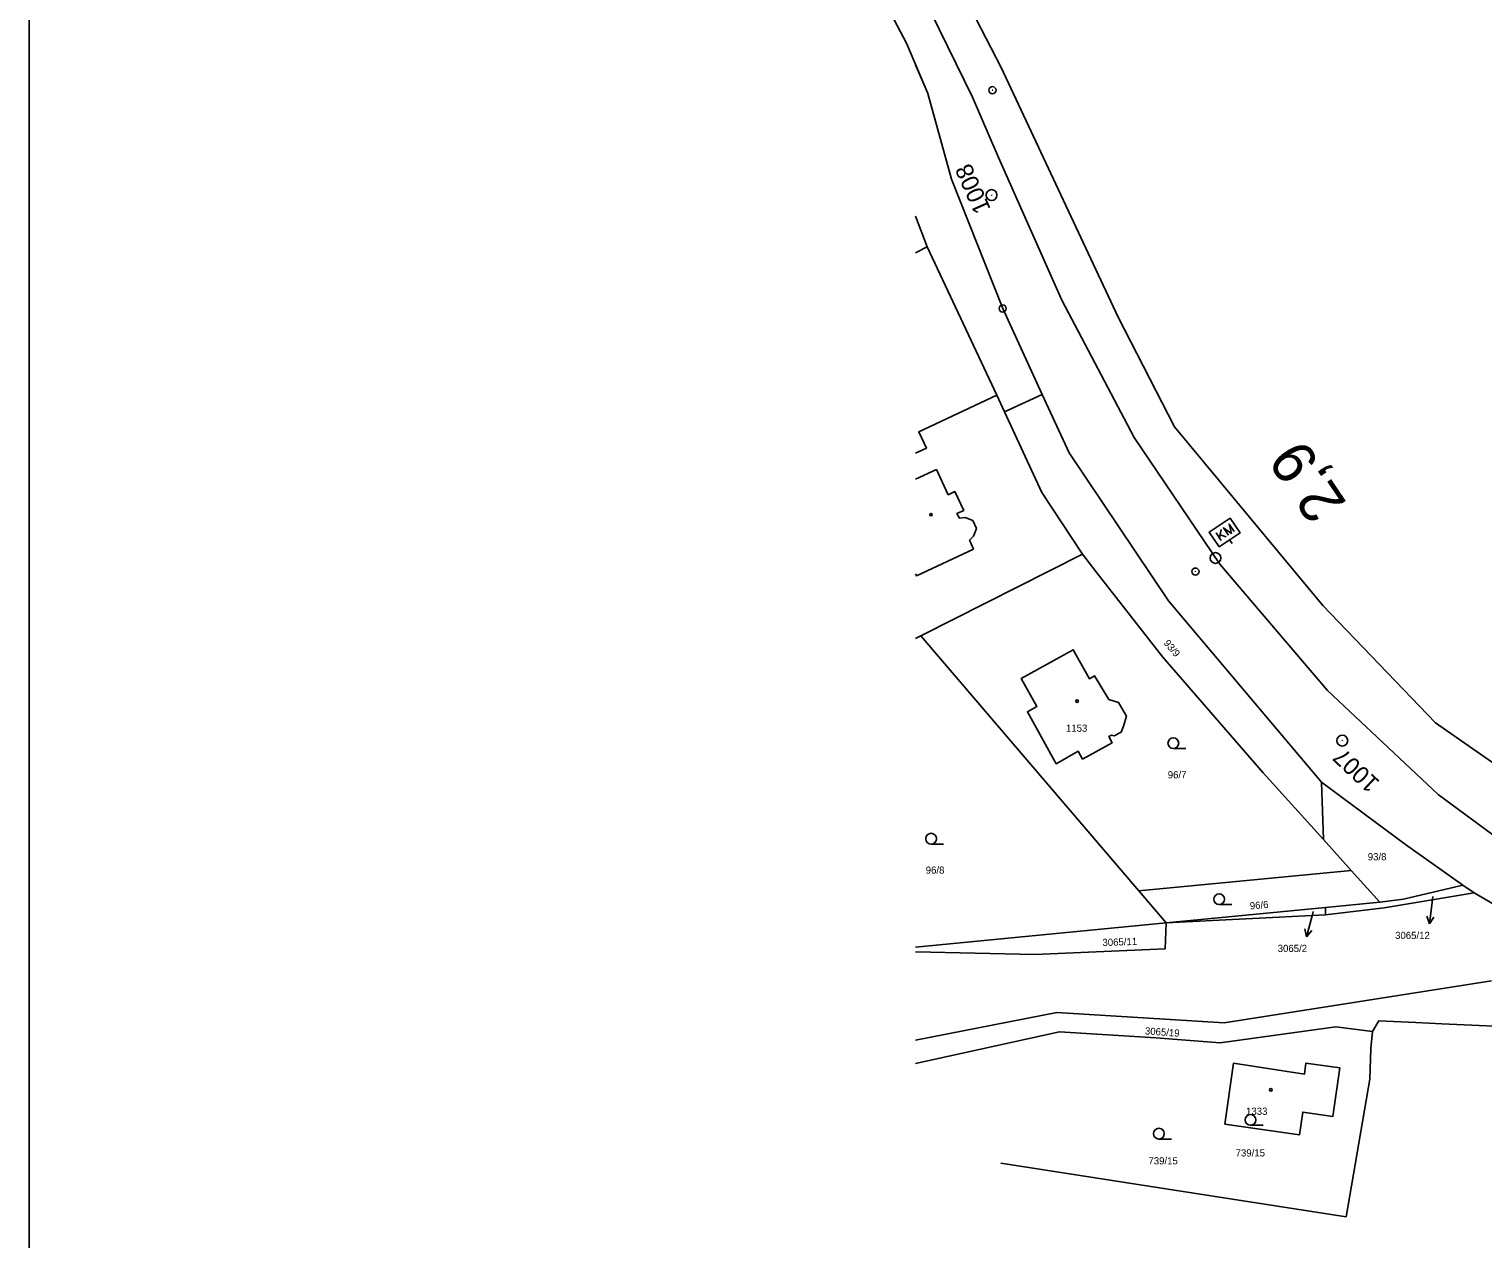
# Model space of a CAD drawing. Extents: x -728800 to -728100, y -1073200 to -1072700.
# Drawn here: x -728800 to -728597.5, y -1073060.8 to -1072892.3 of the extents above; entities that cross this region are included whole.
import ezdxf

# ---------------------------------------------------------------- set-up
doc = ezdxf.new("R2010")
doc.units = 0
for name, color, linetype in [('A1_OBVOD Spravy železnic', 7, 'Continuous'), ('B6_JŽM', 7, 'Continuous'), ('B7_Bodové pole', 7, 'Continuous'), ('K_01_Hranice parcel', 7, 'Continuous'), ('K_02_Parcelní čísla', 7, 'Continuous'), ('K_03_Značky druhu pozemku', 7, 'Continuous'), ('K_05_Značky stavební objekty', 7, 'Continuous'), ('K_07_Pop  PČ popisy', 7, 'Continuous')]:
    doc.layers.add(name, color=color, linetype=linetype)

msp = doc.modelspace()

# ---------------------------------------------------------------- linework, layer by layer
at = {"layer": 'A1_OBVOD Spravy železnic'}
for points in [[(-728681.24, -1072865.51), (-728664.64, -1072897.67), (-728648.31, -1072932.44), (-728640.48, -1072947.72), (-728619.81, -1072972.56), (-728604.14, -1072988.92), (-728582.13, -1073004.22)], [(-728594.83, -1073014.86), (-728598.74, -1073012.6), (-728600.31, -1073011.5), (-728608.33, -1073005.87), (-728620.02, -1072997.18), (-728641.33, -1072971.93), (-728655.13, -1072951.34), (-728658.89, -1072943.19), (-728664.41, -1072931.23), (-728671.52, -1072913.23), (-728674.84, -1072901.32), (-728677.82, -1072894.3), (-728686.27, -1072878.28)]]:
    msp.add_lwpolyline(points, dxfattribs=at)
at = {"layer": 'B6_JŽM'}
for p, q in [((-728665.89, -1072900.84), (-728665.79, -1072900.84)), ((-728664.46, -1072931.23), (-728664.36, -1072931.23)), ((-728634.69, -1072962.47), (-728634, -1072963.51)), ((-728634, -1072962.01), (-728634.23, -1072963.16)), ((-728634.14, -1072962.74), (-728633.3, -1072963.04)), ((-728632.46, -1072963.97), (-728632.81, -1072963.45)), ((-728637.54, -1072967.9), (-728637.59, -1072967.82))]:
    msp.add_line(p, q, dxfattribs=at)
for points in [[(-728800, -1073200), (-728800, -1072700), (-728100, -1072700), (-728100, -1073200), (-728800, -1073200)], [(-728300.81, -1073024.35), (-728320.8, -1073026.91), (-728374.01, -1073033.72), (-728429.1, -1073040.75), (-728461.93, -1073044.27), (-728481.2, -1073044.81), (-728499.35, -1073043.65), (-728506.01, -1073042.74), (-728514.57, -1073041.33), (-728535.85, -1073036), (-728561.35, -1073026.11), (-728583.96, -1073013.52), (-728603.76, -1072998.89), (-728619.19, -1072984.42), (-728634.19, -1072966.82), (-728646.08, -1072949.19), (-728656.18, -1072930.07), (-728664.99, -1072910.23), (-728668.63, -1072901.81), (-728681.25, -1072876.02), (-728691.89, -1072859.66)], [(-728632.96, -1072962.81), (-728633.66, -1072961.77), (-728632.56, -1072962.54), (-728632.87, -1072961.24), (-728632.17, -1072962.28)]]:
    msp.add_lwpolyline(points, dxfattribs=at)
msp.add_lwpolyline([(-728634.25, -1072964.42), (-728635.64, -1072962.37), (-728632.75, -1072960.42), (-728631.36, -1072962.47)], close=True, dxfattribs=at)
for centre, radius in [((-728665.84, -1072900.84), 0.499), ((-728664.41, -1072931.23), 0.499), ((-728634.77, -1072965.97), 0.75), ((-728637.57, -1072967.86), 0.5)]:
    msp.add_circle(centre, radius, dxfattribs=at)
at = {"layer": 'B7_Bodové pole'}
for p, q in [((-728665.94, -1072915.49), (-728665.98, -1072915.4)), ((-728617.07, -1072991.42), (-728617.15, -1072991.35))]:
    msp.add_line(p, q, dxfattribs=at)
for centre in [(-728665.96, -1072915.44), (-728617.11, -1072991.39)]:
    msp.add_circle(centre, 0.756, dxfattribs=at)
at = {"layer": 'K_01_Hranice parcel'}
for p, q in [((-728676.53, -1072918.38), (-728674.91, -1072922.64)), ((-728674.91, -1072922.64), (-728665.22, -1072943.32)), ((-728664.14, -1072945.63), (-728658.89, -1072943.19)), ((-728665.22, -1072943.32), (-728664.14, -1072945.63)), ((-728653.3, -1072965.44), (-728675.82, -1072976.81)), ((-728651.42, -1072967.85), (-728653.3, -1072965.44)), ((-728675.82, -1072976.81), (-728645.47, -1073012.3)), ((-728620.02, -1072997.18), (-728619.75, -1073005.17)), ((-728615.86, -1073009.48), (-728619.75, -1073005.17)), ((-728615.86, -1073009.48), (-728645.47, -1073012.3)), ((-728611.9, -1073013.87), (-728615.86, -1073009.48)), ((-728600.31, -1073011.5), (-728598.74, -1073012.6)), ((-728645.47, -1073012.3), (-728641.66, -1073016.76)), ((-728619.47, -1073014.61), (-728611.9, -1073013.87)), ((-728598.74, -1073012.6), (-728594.83, -1073014.86)), ((-728641.66, -1073016.76), (-728619.47, -1073014.61)), ((-728641.66, -1073016.76), (-728619.45, -1073015.63)), ((-728619.45, -1073015.63), (-728619.47, -1073014.61)), ((-728613.14, -1073034.24), (-728612.89, -1073031.9)), ((-728664.69, -1073050.2), (-728647.33, -1073052.89)), ((-728647.33, -1073052.89), (-728616.56, -1073057.69))]:
    msp.add_line(p, q, dxfattribs=at)
for points in [[(-728658.89, -1072943.19), (-728664.41, -1072931.23), (-728671.52, -1072913.23), (-728674.84, -1072901.32), (-728676.53, -1072897.33)], [(-728676.53, -1072923.46), (-728674.91, -1072922.64)], [(-728658.89, -1072943.19), (-728655.13, -1072951.34), (-728641.33, -1072971.93), (-728620.02, -1072997.18)], [(-728665.22, -1072943.32), (-728676.11, -1072948.38), (-728675.03, -1072950.69), (-728676.53, -1072951.39)], [(-728664.14, -1072945.63), (-728658.98, -1072956.84), (-728653.3, -1072965.44)], [(-728676.53, -1072955.01), (-728673.63, -1072953.66), (-728671.99, -1072957.16), (-728671.07, -1072956.72), (-728669.83, -1072959.34), (-728670.78, -1072959.75), (-728670.44, -1072960.42), (-728669.64, -1072960.34), (-728668.55, -1072960.74), (-728668.06, -1072961.84), (-728668.47, -1072962.95), (-728669.01, -1072963.48), (-728668.94, -1072963.65), (-728668.49, -1072964.73), (-728676.42, -1072968.43), (-728676.53, -1072968.18)], [(-728619.75, -1073005.17), (-728628.12, -1072995.9), (-728642.12, -1072979.76), (-728651.42, -1072967.85)], [(-728675.82, -1072976.81), (-728676.45, -1072977.13), (-728676.53, -1072977.17)], [(-728649.64, -1072985.67), (-728648.26, -1072986.08), (-728647.18, -1072987.97), (-728647.58, -1072989.39), (-728647.91, -1072990.21), (-728648.9, -1072990.74), (-728649.27, -1072990.62), (-728649.61, -1072990.81), (-728649.16, -1072991.69), (-728653.29, -1072993.97), (-728653.91, -1072992.88), (-728656.95, -1072994.61), (-728660.97, -1072987.38), (-728659.66, -1072986.65), (-728661.82, -1072982.76), (-728654.58, -1072978.73), (-728652.33, -1072982.79), (-728651.61, -1072982.39), (-728649.64, -1072985.67)], [(-728620.02, -1072997.18), (-728608.33, -1073005.87), (-728600.31, -1073011.5)], [(-728611.9, -1073013.87), (-728608.61, -1073013.46), (-728600.31, -1073011.5)], [(-728619.45, -1073015.63), (-728611.28, -1073014.65), (-728598.74, -1073012.6)], [(-728641.66, -1073016.76), (-728641.79, -1073020.38), (-728659.93, -1073021.15), (-728676.53, -1073020.82)], [(-728676.53, -1073020.14), (-728641.66, -1073016.76)], [(-728676.53, -1073033.08), (-728656.86, -1073029.26), (-728633.57, -1073030.7), (-728596.32, -1073024.82)], [(-728676.53, -1073036.36), (-728656.52, -1073031.93), (-728643.1, -1073032.77), (-728634.11, -1073033.48), (-728618.03, -1073031.25), (-728612.89, -1073031.9), (-728612.03, -1073030.4), (-728606.88, -1073030.63), (-728603.24, -1073030.8), (-728590.77, -1073031.36), (-728581.13, -1073030.83)], [(-728616.56, -1073057.69), (-728613.27, -1073038.52), (-728613.14, -1073034.24)], [(-728633.49, -1073044.79), (-728623.08, -1073046.28), (-728622.63, -1073043.11), (-728618.43, -1073043.72), (-728617.47, -1073036.95), (-728622.19, -1073036.29), (-728622.39, -1073037.83), (-728632.28, -1073036.32), (-728633.49, -1073044.79)]]:
    msp.add_lwpolyline(points, dxfattribs=at)
at = {"layer": 'K_02_Parcelní čísla'}
for p, q in [((-728604.61, -1073013.9), (-728604.98, -1073016.88)), ((-728604.52, -1073013.11), (-728604.61, -1073013.9)), ((-728621.32, -1073015.79), (-728622.1, -1073018.69)), ((-728621.15, -1073015.17), (-728621.32, -1073015.79)), ((-728604.98, -1073016.88), (-728605.35, -1073015.82)), ((-728604.98, -1073016.88), (-728604.36, -1073015.95)), ((-728622.1, -1073018.69), (-728622.32, -1073017.59)), ((-728622.1, -1073018.69), (-728621.35, -1073017.85))]:
    msp.add_line(p, q, dxfattribs=at)
at = {"layer": 'K_03_Značky druhu pozemku'}
for p, q in [((-728640.64, -1072992.5), (-728638.89, -1072992.5)), ((-728674.38, -1073005.8), (-728672.63, -1073005.8)), ((-728634.26, -1073014.22), (-728632.51, -1073014.22)), ((-728629.9, -1073044.95), (-728628.15, -1073044.95)), ((-728642.65, -1073046.86), (-728640.9, -1073046.86))]:
    msp.add_line(p, q, dxfattribs=at)
for centre, radius in [((-728674.39, -1072959.93), 0.175), ((-728654.05, -1072985.9), 0.175), ((-728640.64, -1072991.75), 0.75), ((-728674.38, -1073005.05), 0.75), ((-728634.26, -1073013.47), 0.75), ((-728627.06, -1073040.01), 0.175), ((-728629.9, -1073044.2), 0.75), ((-728642.65, -1073046.11), 0.75)]:
    msp.add_circle(centre, radius, dxfattribs=at)
at = {"layer": 'K_05_Značky stavební objekty'}
for centre in [(-728674.39, -1072959.93), (-728654.05, -1072985.9), (-728627.06, -1073040.01)]:
    msp.add_circle(centre, 0.175, dxfattribs=at)
at = {"layer": 'K_07_Pop  PČ popisy'}
for p, q in [((-728604.61, -1073013.9), (-728604.98, -1073016.88)), ((-728604.52, -1073013.11), (-728604.61, -1073013.9)), ((-728621.32, -1073015.79), (-728622.1, -1073018.69)), ((-728621.15, -1073015.17), (-728621.32, -1073015.79)), ((-728604.98, -1073016.88), (-728605.35, -1073015.82)), ((-728604.98, -1073016.88), (-728604.36, -1073015.95)), ((-728622.1, -1073018.69), (-728622.32, -1073017.59)), ((-728622.1, -1073018.69), (-728621.35, -1073017.85))]:
    msp.add_line(p, q, dxfattribs=at)

# ---------------------------------------------------------------- texts
at = {"layer": 'B6_JŽM'}
msp.add_text('2,9', height=6, rotation=123.9838, dxfattribs=at).set_placement((-728616.4, -1072958.35))
at = {"layer": 'B7_Bodové pole'}
for s, rotation, p in [('1008', 113.9263, (-728666.03, -1072917.38)), ('1007', 136.8293, (-728611.77, -1072997.12))]:
    msp.add_text(s, height=2.4, rotation=rotation, dxfattribs=at).set_placement(p)
at = {"layer": 'K_02_Parcelní čísla'}
for s, rotation, p in [('93/9', 310, (-728642.05, -1072977.85)), ('96/6', 5, (-728629.95, -1073014.91)), ('3065/11', 2, (-728650.5, -1073020)), ('3065/19', 356, (-728644.63, -1073032.29))]:
    msp.add_text(s, height=1, rotation=rotation, dxfattribs=at).set_placement(p)
for s, p in [('1153', (-728655.6, -1072990.16)), ('96/7', (-728641.42, -1072996.65)), ('93/8', (-728613.57, -1073008.06)), ('96/8', (-728675.13, -1073009.92)), ('3065/12', (-728609.76, -1073019.01)), ('3065/2', (-728626.11, -1073020.82)), ('1333', (-728630.52, -1073043.49)), ('739/15', (-728631.97, -1073049.29)), ('739/15', (-728644.11, -1073050.39))]:
    msp.add_text(s, height=1, dxfattribs=at).set_placement(p)

doc.saveas('drawing.dxf')
